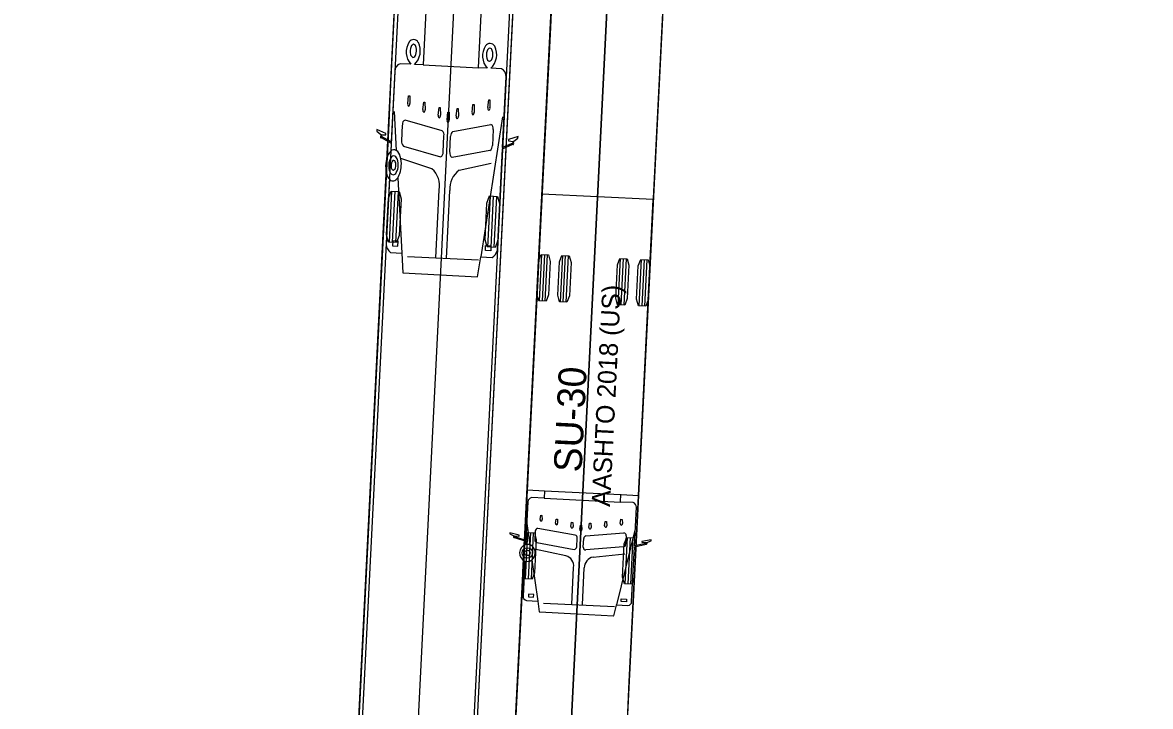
# Model space of a CAD drawing. Extents: x 260275 to 261282, y 610916 to 614143.
# Drawn here: x 260986.2 to 261067.3, y 611701.9 to 611751.1 of the extents above; entities that cross this region are included whole.
import ezdxf

# ---------------------------------------------------------------- set-up
doc = ezdxf.new("R2010")
doc.units = 0
doc.layers.add('GE_X_Alignment', color=7, linetype='Continuous')
doc.layers.add('UT_X_Water_Cells', color=7, linetype='Continuous')

msp = doc.modelspace()

# ---------------------------------------------------------------- linework, layer by layer
at = {"layer": 'GE_X_Alignment'}
msp.add_line((260986.249, 610915.954), (261148.276, 614142.838), dxfattribs=at)
at = {"layer": 'UT_X_Water_Cells'}
for p, q in [((261044.031, 612066.726), (261023.69, 611661.632)), ((261031.95, 612045.486), (261010.925, 611626.741)), ((261014.137, 611748.05), (261013.363, 611748.089)), ((261015.024, 611748.006), (261018.993, 611747.806)), ((261020.654, 611747.723), (261019.88, 611747.762)), ((261013.911, 611745.235), (261013.974, 611745.782)), ((261013.974, 611745.782), (261014.057, 611745.778)), ((261014.057, 611745.778), (261014.065, 611745.227)), ((261015.007, 611744.794), (261015.071, 611745.341)), ((261015.071, 611745.341), (261015.153, 611745.337)), ((261015.153, 611745.337), (261015.161, 611744.786)), ((261019.669, 611744.946), (261019.732, 611745.493)), ((261019.732, 611745.493), (261019.815, 611745.489)), ((261019.815, 611745.489), (261019.823, 611744.938)), ((261012.941, 611744.667), (261013.094, 611741.867)), ((261016.106, 611744.404), (261016.17, 611744.951)), ((261016.17, 611744.951), (261016.252, 611744.947)), ((261016.252, 611744.947), (261016.261, 611744.396)), ((261016.738, 611744.063), (261016.802, 611744.61)), ((261016.802, 611744.61), (261016.884, 611744.606)), ((261016.884, 611744.606), (261016.892, 611744.056)), ((261017.401, 611744.339), (261017.465, 611744.886)), ((261017.465, 611744.886), (261017.547, 611744.882)), ((261017.547, 611744.882), (261017.555, 611744.331)), ((261018.533, 611744.592), (261018.597, 611745.164)), ((261018.597, 611745.164), (261018.68, 611745.16)), ((261018.68, 611745.16), (261018.687, 611744.584)), ((261013.527, 611743.685), (261013.47, 611742.556)), ((261016.386, 611743.267), (261013.727, 611744.046)), ((261017.164, 611743.228), (261019.887, 611743.736)), ((261020.731, 611744.276), (261019.16, 611734.207)), ((261011.995, 611742.985), (261011.976, 611743.003)), ((261012.021, 611742.985), (261011.995, 611742.985)), ((261016.462, 611741.76), (261016.519, 611742.889)), ((261016.937, 611741.736), (261016.993, 611742.866)), ((261020.05, 611743.358), (261019.993, 611742.228)), ((261013.603, 611742.178), (261016.262, 611741.399)), ((261021.478, 611742.51), (261021.503, 611742.508)), ((261021.503, 611742.508), (261021.525, 611742.523)), ((261015.656, 611740.537), (261013.415, 611741.286)), ((261019.823, 611741.866), (261017.1, 611741.357)), ((261017.616, 611740.438), (261019.909, 611740.957)), ((261012.597, 611739.802), (261012.361, 611735.107)), ((261013.201, 611739.905), (261013.496, 611734.492)), ((261012.599, 611735.278), (261012.783, 611738.94)), ((261012.828, 611735.266), (261013.012, 611738.928)), ((261013.057, 611735.255), (261013.24, 611738.917)), ((261015.934, 611734.144), (261016.179, 611739.029)), ((261016.699, 611734.105), (261016.944, 611738.991)), ((261019.673, 611734.923), (261019.857, 611738.585)), ((261019.902, 611734.911), (261020.086, 611738.573)), ((261020.131, 611734.9), (261020.315, 611738.562)), ((261012.85, 611735.361), (261012.832, 611735.005)), ((261012.832, 611735.005), (261013.21, 611734.986)), ((261013.228, 611735.342), (261012.85, 611735.361)), ((261013.21, 611734.986), (261013.228, 611735.342)), ((261019.494, 611734.671), (261019.512, 611735.026)), ((261019.872, 611734.652), (261019.494, 611734.671)), ((261019.512, 611735.026), (261019.89, 611735.007)), ((261019.89, 611735.007), (261019.872, 611734.652)), ((261013.9, 611734.246), (261018.999, 611733.99)), ((261023.38, 611731.061), (261023.547, 611734.39)), ((261023.588, 611731.05), (261023.755, 611734.379)), ((261023.796, 611731.04), (261023.963, 611734.369)), ((261024.878, 611730.985), (261025.045, 611734.315)), ((261025.086, 611730.975), (261025.253, 611734.304)), ((261025.294, 611730.965), (261025.462, 611734.294)), ((261029.04, 611730.777), (261029.207, 611734.106)), ((261029.248, 611730.766), (261029.415, 611734.095)), ((261029.456, 611730.756), (261029.623, 611734.085)), ((261030.538, 611730.701), (261030.705, 611734.03)), ((261030.746, 611730.691), (261030.913, 611734.02)), ((261030.954, 611730.68), (261031.121, 611734.01)), ((261013.574, 611733.059), (261018.938, 611732.79)), ((261023.715, 611716.875), (261029.2, 611716.599)), ((261023.741, 611717.406), (261029.226, 611717.13)), ((261023.424, 611715.347), (261023.475, 611715.645)), ((261023.475, 611715.645), (261023.557, 611715.641)), ((261023.557, 611715.641), (261023.578, 611715.34)), ((261024.529, 611715.081), (261024.58, 611715.379)), ((261024.58, 611715.379), (261024.663, 611715.375)), ((261024.663, 611715.375), (261024.683, 611715.074)), ((261029.182, 611715.058), (261029.233, 611715.356)), ((261029.233, 611715.356), (261029.315, 611715.352)), ((261029.315, 611715.352), (261029.336, 611715.051)), ((261022.377, 611711.086), (261022.544, 611714.415)), ((261022.468, 611715.059), (261022.684, 611713.525)), ((261022.585, 611711.075), (261022.752, 611714.405)), ((261023.076, 611714.509), (261023.045, 611713.893)), ((261025.941, 611714.215), (261023.268, 611714.702)), ((261025.636, 611714.843), (261025.687, 611715.141)), ((261025.687, 611715.141), (261025.769, 611715.137)), ((261025.769, 611715.137), (261025.79, 611714.835)), ((261026.275, 611714.643), (261026.326, 611714.94)), ((261026.326, 611714.94), (261026.408, 611714.936)), ((261026.408, 611714.936), (261026.429, 611714.635)), ((261026.931, 611714.778), (261026.982, 611715.076)), ((261026.982, 611715.076), (261027.064, 611715.072)), ((261027.064, 611715.072), (261027.085, 611714.77)), ((261028.056, 611714.891), (261028.107, 611715.202)), ((261028.107, 611715.202), (261028.189, 611715.198)), ((261028.189, 611715.198), (261028.21, 611714.883)), ((261030.258, 611714.668), (261028.918, 611709.2)), ((261022.793, 611711.065), (261022.96, 611714.394)), ((261023.186, 611713.684), (261025.86, 611713.197)), ((261026.051, 611713.39), (261026.082, 611714.006)), ((261026.526, 611713.366), (261026.557, 611713.982)), ((261026.719, 611714.176), (261029.427, 611714.392)), ((261029.535, 611710.726), (261029.702, 611714.056)), ((261029.599, 611714.181), (261029.568, 611713.566)), ((261029.743, 611710.716), (261029.91, 611714.045)), ((261029.951, 611710.706), (261030.118, 611714.035)), ((261025.274, 611712.74), (261023.018, 611713.2)), ((261029.406, 611713.371), (261026.697, 611713.155)), ((261027.234, 611712.641), (261029.513, 611712.872)), ((261022.333, 611712.36), (261022.206, 611709.841)), ((261022.836, 611712.45), (261023.254, 611709.485)), ((261025.698, 611709.239), (261025.831, 611711.904)), ((261026.462, 611709.201), (261026.596, 611711.865)), ((261022.589, 611709.974), (261022.579, 611709.781)), ((261022.579, 611709.781), (261022.957, 611709.762)), ((261022.967, 611709.955), (261022.589, 611709.974)), ((261022.957, 611709.762), (261022.967, 611709.955)), ((261029.241, 611709.446), (261029.251, 611709.64)), ((261029.251, 611709.64), (261029.629, 611709.621)), ((261029.629, 611709.621), (261029.619, 611709.427)), ((261023.663, 611709.341), (261028.762, 611709.085)), ((261029.619, 611709.427), (261029.241, 611709.446))]:
    msp.add_line(p, q, dxfattribs=at)
for points in [[(261009.34, 611680.102), (261030.965, 612110.617)], [(261039.447, 612110.045), (261018.12, 611685.301)], [(261020.965, 611687.133), (261041.34, 612092.893)], [(261049.322, 612092.345), (261028.546, 611678.469)], [(261019.622, 611747.775), (261018.993, 611747.806), (261019.524, 611758.393), (261015.556, 611758.592), (261015.024, 611748.006), (261014.395, 611748.037)], [(261024.325, 611754.039), (261024.158, 611750.71), (261023.991, 611747.382), (261023.824, 611744.053), (261023.657, 611740.724), (261023.49, 611737.396), (261023.322, 611734.067), (261023.155, 611730.739), (261022.988, 611727.41), (261022.821, 611724.081), (261022.654, 611720.753), (261022.487, 611717.424), (261022.32, 611714.095), (261022.153, 611710.767), (261021.985, 611707.438), (261021.818, 611704.11), (261021.651, 611700.781)], [(261024.325, 611754.036), (261024.158, 611750.707), (261023.991, 611747.379), (261023.824, 611744.05), (261023.657, 611740.721), (261023.489, 611737.393), (261023.322, 611734.064), (261023.155, 611730.735), (261022.988, 611727.407), (261022.821, 611724.078), (261022.654, 611720.75), (261022.487, 611717.421), (261022.32, 611714.092), (261022.152, 611710.764), (261021.985, 611707.435), (261021.818, 611704.106), (261021.651, 611700.778)], [(261032.315, 611753.638), (261032.148, 611750.309), (261031.981, 611746.98), (261031.814, 611743.652), (261031.647, 611740.323), (261031.48, 611736.995), (261031.312, 611733.666), (261031.145, 611730.337), (261030.978, 611727.009), (261030.811, 611723.68), (261030.644, 611720.351), (261030.477, 611717.023), (261030.31, 611713.694), (261030.142, 611710.366), (261029.975, 611707.037), (261029.808, 611703.708), (261029.641, 611700.38)], [(261032.315, 611753.635), (261032.148, 611750.306), (261031.981, 611746.977), (261031.814, 611743.649), (261031.647, 611740.32), (261031.479, 611736.991), (261031.312, 611733.663), (261031.145, 611730.334), (261030.978, 611727.006), (261030.811, 611723.677), (261030.644, 611720.348), (261030.477, 611717.02), (261030.309, 611713.691), (261030.142, 611710.363), (261029.975, 611707.034), (261029.808, 611703.705), (261029.641, 611700.377)], [(261013.023, 611753.286), (261012.856, 611749.957), (261012.689, 611746.628), (261012.522, 611743.3), (261012.355, 611739.971), (261012.188, 611736.642), (261012.02, 611733.314), (261011.853, 611729.985), (261011.686, 611726.657), (261011.519, 611723.328), (261011.352, 611719.999), (261011.185, 611716.671), (261011.018, 611713.342), (261010.851, 611710.013), (261010.683, 611706.685), (261010.516, 611703.356), (261010.349, 611700.027)], [(261013.247, 611752.765), (261013.08, 611749.436), (261012.913, 611746.108), (261012.746, 611742.779), (261012.579, 611739.45), (261012.412, 611736.122), (261012.245, 611732.793), (261012.078, 611729.464), (261011.91, 611726.136), (261011.743, 611722.807), (261011.576, 611719.479), (261011.409, 611716.15), (261011.242, 611712.821), (261011.075, 611709.493), (261010.908, 611706.164), (261010.74, 611702.835), (261010.573, 611699.507)], [(261021.513, 611752.859), (261021.345, 611749.531), (261021.178, 611746.202), (261021.011, 611742.874), (261020.844, 611739.545), (261020.677, 611736.216), (261020.51, 611732.888), (261020.343, 611729.559), (261020.176, 611726.23), (261020.008, 611722.902), (261019.841, 611719.573), (261019.674, 611716.244), (261019.507, 611712.916), (261019.34, 611709.587), (261019.173, 611706.258), (261019.006, 611702.93), (261018.838, 611699.601)], [(261021.237, 611752.364), (261021.07, 611749.035), (261020.903, 611745.707), (261020.736, 611742.378), (261020.569, 611739.049), (261020.402, 611735.721), (261020.235, 611732.392), (261020.067, 611729.063), (261019.9, 611725.735), (261019.733, 611722.406), (261019.566, 611719.077), (261019.399, 611715.749), (261019.232, 611712.42), (261019.065, 611709.091), (261018.897, 611705.763), (261018.73, 611702.434), (261018.563, 611699.105)], [(261012.986, 611747.55), (261012.731, 611742.474), (261012.028, 611742.866), (261012.027, 611742.866)], [(261021.46, 611742.392), (261021.46, 611742.392), (261020.721, 611742.073), (261020.976, 611747.148)], [(261012.018, 611742.903), (261012.021, 611742.985), (261012.342, 611742.985), (261012.347, 611743.088), (261011.699, 611743.378), (261011.693, 611743.258), (261011.976, 611743.003), (261011.972, 611742.916)], [(261012.006, 611742.78), (261012.726, 611742.375), (261012.697, 611741.802)], [(261021.52, 611742.436), (261021.525, 611742.523), (261021.831, 611742.749), (261021.838, 611742.869), (261021.164, 611742.645), (261021.158, 611742.542), (261021.478, 611742.51), (261021.473, 611742.429)], [(261020.351, 611734.706), (261020.716, 611741.974), (261021.472, 611742.305)], [(261030.098, 611716.554), (261029.203, 611716.599), (261029.2, 611716.603), (261029.226, 611717.129), (261029.237, 611717.13), (261030.479, 611717.067), (261031.546, 611738.327), (261027.551, 611738.528), (261023.557, 611738.728), (261022.489, 611717.468), (261023.73, 611717.406), (261023.741, 611717.405), (261023.715, 611716.878), (261023.712, 611716.875), (261022.817, 611716.92)], [(261012.682, 611734.533), (261013.496, 611734.492), (261013.574, 611733.072)], [(261013.574, 611733.059), (261018.938, 611732.79), (261019.16, 611734.207), (261019.973, 611734.167)], [(261022.546, 611716.617), (261022.407, 611713.847), (261022.402, 611713.835), (261021.597, 611714.095), (261021.596, 611714.095)], [(261031.029, 611713.622), (261031.029, 611713.622), (261030.202, 611713.443), (261030.197, 611713.456), (261030.337, 611716.226)], [(261021.586, 611714.116), (261021.588, 611714.16), (261021.588, 611714.161), (261021.906, 611714.153), (261021.908, 611714.153), (261021.911, 611714.209), (261021.908, 611714.21), (261021.26, 611714.382), (261021.257, 611714.383), (261021.254, 611714.318), (261021.542, 611714.172), (261021.542, 611714.171), (261021.54, 611714.124)], [(261021.577, 611714.049), (261021.578, 611714.049), (261022.397, 611713.781), (261022.403, 611713.769), (261022.392, 611713.541)], [(261031.088, 611713.644), (261031.091, 611713.691), (261031.091, 611713.692), (261031.392, 611713.809), (261031.395, 611713.874), (261031.393, 611713.874), (261030.731, 611713.767), (261030.727, 611713.766), (261030.725, 611713.711), (261030.727, 611713.71), (261031.044, 611713.686), (261031.044, 611713.685), (261031.041, 611713.641)], [(261029.996, 611709.45), (261030.194, 611713.378), (261030.201, 611713.389), (261031.043, 611713.574), (261031.044, 611713.574)], [(261022.444, 611709.525), (261023.251, 611709.485), (261023.255, 611709.48), (261023.365, 611708.702), (261023.407, 611708.698), (261026.047, 611708.565), (261028.687, 611708.433), (261028.73, 611708.433), (261028.917, 611709.196), (261028.921, 611709.2), (261029.728, 611709.16)]]:
    msp.add_lwpolyline(points, dxfattribs=at)
for points in [[(261013.113, 611735.252), (261012.542, 611735.281), (261012.396, 611735.802), (261012.528, 611738.439), (261012.726, 611738.943), (261013.297, 611738.914), (261013.444, 611738.393), (261013.311, 611735.756)], [(261020.188, 611734.897), (261019.617, 611734.925), (261019.47, 611735.447), (261019.603, 611738.084), (261019.8, 611738.588), (261020.372, 611738.559), (261020.518, 611738.038), (261020.386, 611735.401)], [(261023.848, 611731.037), (261023.329, 611731.063), (261023.195, 611731.537), (261023.316, 611733.934), (261023.496, 611734.392), (261024.015, 611734.366), (261024.148, 611733.892), (261024.028, 611731.495)], [(261025.346, 611730.962), (261024.827, 611730.988), (261024.694, 611731.462), (261024.814, 611733.859), (261024.994, 611734.317), (261025.513, 611734.291), (261025.646, 611733.817), (261025.526, 611731.42)], [(261029.507, 611730.753), (261028.988, 611730.779), (261028.855, 611731.253), (261028.975, 611733.65), (261029.155, 611734.108), (261029.675, 611734.082), (261029.808, 611733.608), (261029.687, 611731.211)], [(261031.006, 611730.678), (261030.486, 611730.704), (261030.353, 611731.178), (261030.473, 611733.575), (261030.653, 611734.033), (261031.173, 611734.007), (261031.306, 611733.533), (261031.185, 611731.136)], [(261022.845, 611711.062), (261022.326, 611711.088), (261022.192, 611711.562), (261022.313, 611713.959), (261022.493, 611714.418), (261023.012, 611714.392), (261023.145, 611713.918), (261023.025, 611711.521)], [(261030.003, 611710.703), (261029.483, 611710.729), (261029.35, 611711.203), (261029.47, 611713.6), (261029.65, 611714.058), (261030.17, 611714.032), (261030.303, 611713.558), (261030.182, 611711.161)]]:
    msp.add_lwpolyline(points, close=True, dxfattribs=at)
for radius in [0.374, 0.193]:
    msp.add_circle((261022.507, 611712.943), radius, dxfattribs=at)
for centre, radius, start, end in [((261015.15, 611748.933), 1.344, 147.53526, 221.09006), ((261014.336, 611749.444), 0.383, 27.59628, 146.65472), ((261014.939, 611748.984), 0.86, 155.59014, 195.55953), ((261014.37, 611749.26), 0.228, 97.92836, 159.8232), ((261014.263, 611749.235), 0.262, 6.80834, 73.33353), ((261013.476, 611749.017), 1.344, 313.16094, 26.71574), ((261013.671, 611749.05), 0.879, 339.66236, 14.25761), ((261020.635, 611748.658), 1.344, 147.53526, 221.09006), ((261019.821, 611749.16), 0.387, 28.62104, 145.62996), ((261018.961, 611748.742), 1.344, 313.16094, 26.71574), ((261014.393, 611748.82), 0.29, 193.32121, 249.48124), ((261014.253, 611748.792), 0.247, 278.8428, 348.7219), ((261020.443, 611748.709), 0.879, 159.9934, 194.58864), ((261019.839, 611748.512), 0.247, 185.52911, 255.4082), ((261019.873, 611748.953), 0.262, 100.91747, 167.44267), ((261019.702, 611748.553), 0.29, 284.76976, 340.92979), ((261019.77, 611748.989), 0.228, 14.4278, 76.32264), ((261019.176, 611748.771), 0.86, 338.69148, 18.66086), ((261013.557, 611747.552), 0.571, 109.81853, 180.21012), ((261020.407, 611747.208), 0.571, 354.04089, 64.43248), ((261014.096, 611745.184), 0.192, 164.57524, 232.04981), ((261013.876, 611745.195), 0.192, 302.17384, 9.70311), ((261015.193, 611744.743), 0.192, 164.57524, 232.04981), ((261014.972, 611744.754), 0.192, 302.17384, 9.70311), ((261016.292, 611744.353), 0.192, 164.57524, 232.04981), ((261016.071, 611744.364), 0.192, 302.17384, 9.70311), ((261018.719, 611744.566), 0.192, 164.5479, 232.07716), ((261018.498, 611744.577), 0.192, 302.20119, 9.67576), ((261019.854, 611744.895), 0.192, 164.5479, 232.07716), ((261019.634, 611744.906), 0.192, 302.20119, 9.67576), ((261013.86, 611743.74), 0.334, 113.39037, 185.98833), ((261016.924, 611744.012), 0.192, 164.57524, 232.04981), ((261016.703, 611744.023), 0.192, 302.20119, 9.67576), ((261017.586, 611744.288), 0.192, 164.5479, 232.07716), ((261017.366, 611744.299), 0.192, 302.20119, 9.67576), ((261019.724, 611743.445), 0.334, 348.26267, 60.86063), ((261012.077, 611742.843), 0.127, 145.02093, 209.23008), ((261011.986, 611742.794), 0.0244, 212.94354, 326.25791), ((261011.917, 611742.858), 0.11, 4.06966, 24.17798), ((261016.127, 611742.965), 0.397, 351.20134, 49.36435), ((261017.391, 611742.902), 0.397, 124.88665, 183.04966), ((261013.867, 611742.483), 0.403, 169.66784, 229.12579), ((261019.591, 611742.196), 0.403, 305.12521, 4.58316), ((261021.568, 611742.374), 0.11, 150.07302, 170.18134), ((261021.494, 611742.316), 0.0244, 207.99309, 321.30746), ((261021.408, 611742.374), 0.127, 325.02093, 29.23008), ((261014.533, 611740.708), 2.204, 164.32456, 183.95974), ((261013.315, 611741.116), 0.924, 132.02262, 168.30076), ((261013.462, 611740.822), 0.913, 140.43513, 180.69541), ((261012.932, 611741.614), 0.301, 57.35677, 141.25506), ((261012.914, 611741.28), 0.199, 40.92879, 141.5681), ((261012.905, 611741.027), 0.12, 12.10162, 157.57965), ((261012.325, 611740.873), 0.914, 353.95993, 36.01791), ((261012.604, 611741.236), 0.799, 12.92493, 52.19257), ((261011.444, 611740.879), 2.012, 356.76687, 15.44978), ((261016.121, 611741.707), 0.342, 295.59721, 5.52369), ((261017.271, 611741.65), 0.342, 168.72731, 238.65379), ((261014.062, 611740.662), 1.731, 183.5106, 198.70836), ((261013.782, 611740.741), 1.234, 176.75519, 194.33734), ((261012.989, 611740.495), 0.407, 188.35614, 251.16055), ((261013.346, 611740.766), 0.631, 150.93378, 193.73431), ((261012.95, 611740.647), 0.22, 188.13535, 249.83363), ((261012.79, 611740.697), 0.27, 288.27444, 1.01824), ((261012.453, 611740.815), 0.617, 349.4131, 22.60389), ((261012.137, 611740.809), 1.098, 330.39127, 358.28386), ((261011.405, 611740.857), 2.049, 341.50654, 357.43184), ((261014.574, 611739.316), 1.631, 349.85894, 48.44967), ((261018.57, 611739.116), 1.631, 125.80134, 184.39207), ((261013.114, 611740.3), 0.719, 195.6559, 223.91288), ((261012.858, 611740), 0.328, 217.21385, 266.11819), ((261012.832, 611740.053), 0.38, 270.45588, 320.97941), ((261012.847, 611740.376), 0.268, 272.19814, 335.87577), ((261012.323, 611740.524), 1.074, 318.58211, 342.85096), ((261013.15, 611735.171), 0.792, 184.65895, 233.81442), ((261019.572, 611734.849), 0.792, 300.43659, 349.59206), ((261022.869, 611716.601), 0.323, 99.2771, 177.1255), ((261030.014, 611716.242), 0.323, 357.1255, 74.97391), ((261023.512, 611715.325), 0.091, 165.44206, 259.60593), ((261023.488, 611715.326), 0.0909, 274.60942, 8.84462), ((261023.26, 611714.517), 0.184, 87.71808, 182.58934), ((261024.617, 611715.058), 0.091, 165.44206, 259.60593), ((261024.594, 611715.06), 0.0909, 274.60942, 8.84462), ((261025.724, 611714.82), 0.091, 165.44206, 259.60593), ((261025.7, 611714.822), 0.0909, 274.60942, 8.84462), ((261026.363, 611714.62), 0.091, 165.44206, 259.60593), ((261026.339, 611714.621), 0.091, 274.64508, 8.80895), ((261027.019, 611714.755), 0.0909, 165.40639, 259.64159), ((261026.995, 611714.757), 0.091, 274.64508, 8.80895), ((261028.144, 611714.881), 0.0909, 165.40639, 259.64159), ((261028.12, 611714.883), 0.091, 274.64508, 8.80895), ((261029.27, 611715.035), 0.0909, 165.40639, 259.64159), ((261029.246, 611715.037), 0.091, 274.64508, 8.80895), ((261021.56, 611714.087), 0.0418, 117.61865, 294.63358), ((261021.554, 611714.087), 0.0434, 11.03902, 41.7118), ((261023.236, 611713.87), 0.193, 173.06859, 254.98308), ((261025.891, 611714.029), 0.193, 353.06366, 74.98801), ((261026.75, 611713.986), 0.193, 99.26299, 181.18734), ((261029.416, 611714.208), 0.184, 351.66167, 86.53293), ((261031.071, 611713.609), 0.0434, 132.53921, 163.21198), ((261031.065, 611713.61), 0.0418, 239.61742, 56.63235), ((261022.574, 611712.94), 0.628, 106.8788, 247.3705), ((261022.512, 611713.03), 0.524, 49.38452, 103.18459), ((261022.438, 611712.938), 0.629, 309.17109, 357.86038), ((261022.439, 611712.954), 0.63, 356.4803, 48.88311), ((261025.867, 611713.382), 0.184, 267.72364, 2.58377), ((261026.709, 611713.339), 0.184, 171.66723, 266.52737), ((261029.375, 611713.562), 0.193, 279.26792, 1.18241), ((261022.503, 611712.857), 0.526, 251.07067, 309.31667), ((261025.064, 611711.996), 0.773, 353.15088, 74.23504), ((261027.369, 611711.88), 0.773, 100.01597, 181.10013), ((261022.485, 611709.804), 0.282, 172.49767, 261.5771), ((261029.715, 611709.441), 0.282, 272.67391, 1.75333)]:
    msp.add_arc(centre, radius, start, end, dxfattribs=at)
for centre, major_axis, start_param, end_param in [((261011.989, 611742.847), (-0.0039, -0.0781), 2.398717, 3.668019), ((261011.989, 611742.847), (0.0039, 0.0781), 3.71124, 4.981984), ((261021.497, 611742.37), (-0.0039, -0.0781), 4.442794, 5.713538), ((261021.497, 611742.37), (0.0039, 0.0781), 5.756759, 7.026061)]:
    msp.add_ellipse(centre, major_axis=major_axis, ratio=0.5, start_param=start_param, end_param=end_param, dxfattribs=at)

# ---------------------------------------------------------------- texts
for s, height, p in [('AASHTO 2018 (US)', 1.33333, (261028.442, 611716.241)), ('SU-30', 2, (261026.396, 611718.703))]:
    msp.add_text(s, height=height, rotation=87.1255, dxfattribs=at).set_placement(p)

doc.saveas('drawing.dxf')
